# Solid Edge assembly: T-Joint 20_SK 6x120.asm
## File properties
Author: fknapp
Template: iso metric assembly.asm
Last saved by: fknapp
Revision: 5
Application: Solid Edge
Username: fknapp
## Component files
Rundzylinderscheibe_8er_Schraube_45_V3.par
SK_Schraube_6x120.par
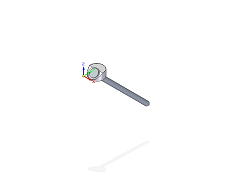
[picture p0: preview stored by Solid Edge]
